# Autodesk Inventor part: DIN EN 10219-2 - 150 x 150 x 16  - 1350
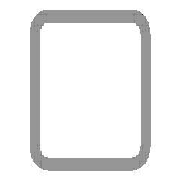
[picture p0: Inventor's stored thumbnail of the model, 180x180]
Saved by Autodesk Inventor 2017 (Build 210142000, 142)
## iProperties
_CCFamilyMember: 76
_CCFamilyDisplayName: DIN EN 10219-2 (Square Hollow Section - Cold Formed) - Cold formed welded structural hollow sections of non-alloy and fine grain structural steel
_FrameMemberDoc: Frame Member File
_Version: 15.0.0
_GetPNFromCC: 1
Created: 2017-11
Part Number: DIN EN 10219-2 - 150 x 150 x 16  - 1350
Material: Steel, Mild
Description: Cold formed welded structural hollow sections of non-alloy and fine grain structural steel
Document SubType Name: Modeling
Standard: DIN
Designer: iusti
Standard Revision: 2006-07
Standards Organization: DIN
Language: en-US
Size Designation: 150 x 150 x 16
Categories: <MemberInstance><Categories><Category DisplayName="Structural Shapes" InternalName="089c4875-fa83-4c05-b084-43b9cc11f5ed" Mnemonic="GRDR"><CategoryParameter Dis
Stock Number: 150 x 150 x 16
Mass: 79240 g
Surface Area: 12767.4 cm^2
Volume: 10094.3 cm^3
Density: 7.85 g/cm^3
Appearance: Semi-Polished
IsCustomPart: 1
G_L: 1350.000 mm
G_W: 150.000 mm
G_H: 150.000 mm
+A865EAF7-CA2A-45A3-BC1A-64379BFC4A12+CUTDETAIL1: Cut
+34F438F3-E4A3-435A-9615-239FC3982D01+CUTDETAIL2: Cut
Author: iusti
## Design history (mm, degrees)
node "Start plane"
node "End plane"
sketch "Sketch"
  geometry: L1 (-75, -27)-(-75, 27); L2 (-27, 75)-(27, 75); L3 (75, 27)-(75, -27); L4 (27, -75)-(-27, -75); L5 (-27, 59)-(27, 59); L6 (59, 27)-(59, -27); L7 (27, -59)-(-27, -59); L8 (-59, -27)-(-59, 27); L9 (0, 118.918)-(0, -118.918) reference; L10 (-118.918, 0)-(118.918, 0) reference; A1 r 48 centre (-27, -27) between (-75, -27) and (-27, -75); A2 r 48 centre (-27, 27) between (-27, 75) and (-75, 27); A3 r 48 centre (27, 27) between (75, 27) and (27, 75); A4 r 48 centre (27, -27) between (27, -75) and (75, -27); A5 r 32 centre (-27, 27) between (-27, 59) and (-59, 27); A6 r 32 centre (27, 27) between (59, 27) and (27, 59); A7 r 32 centre (27, -27) between (27, -59) and (59, -27); A8 r 32 centre (-27, -27) between (-59, -27) and (-27, -59)
  constraints: 16 end point, 16 point on circle, 8 centre point, 8 tangent, 4 parallel, 3 equal radius, 2 perpendicular, 7 other
  dimensions: "d7" = 48 radius of A1 (= G_IR); "d10" = 150 distance between parallel lines of L2 L4 (= G_H); "d11" = 150 distance between parallel lines of L1 L3 (= G_W); "d12" = 16 distance between parallel lines of L3 L6 (= G_T); "d15" = 75 distance between parallel lines of L2 L10 (= 0.5 x d10); "d16" = 75 distance between parallel lines of L9 L3 (= 0.5 x d11)
extrude "Body" new body sketch "Sketch" stored distance "d3" = 1350 (= G_L); taper "d4" = 0 deg
node "Driven Length"
  sketch "Sketch3"
    geometry: L1 (0, 0)-(10, 0) reference
    constraints: 2 end point, 1 horizontal
  workplane "Work Plane3"
  sketch "Sketch4"
    geometry: L1 (-2, 75)-(12, 75) reference; L2 (-2, 1425)-(12, 1425) reference
    dimensions: "d18" = 1350 distance between parallel lines of L1 L2 (derived)
workplane "Work Plane4"
split "Split1"
workplane "Work Plane5"
split "Split2"
body "Solid1"
other parameters: "G_W" = 150 [user parameter; used in 1 equation term], "G_H" = 150 [user parameter; used in 1 equation term], "G_T" = 16 [user parameter; used in 1 equation term], "G_IR" = 48 [user parameter; used in 1 equation term], "G_L" = 1350 (= d18) [user parameter; used in 1 equation term], "G_OFFSET_START" = -75 [user parameter; used in 1 equation term], "G_OFFSET_END" = -75 [user parameter; used in 1 equation term], "d13" = 75 (= -G_OFFSET_START), "d14" = 1425 (= G_OFFSET_END + B_L), "d17" = 90 deg
